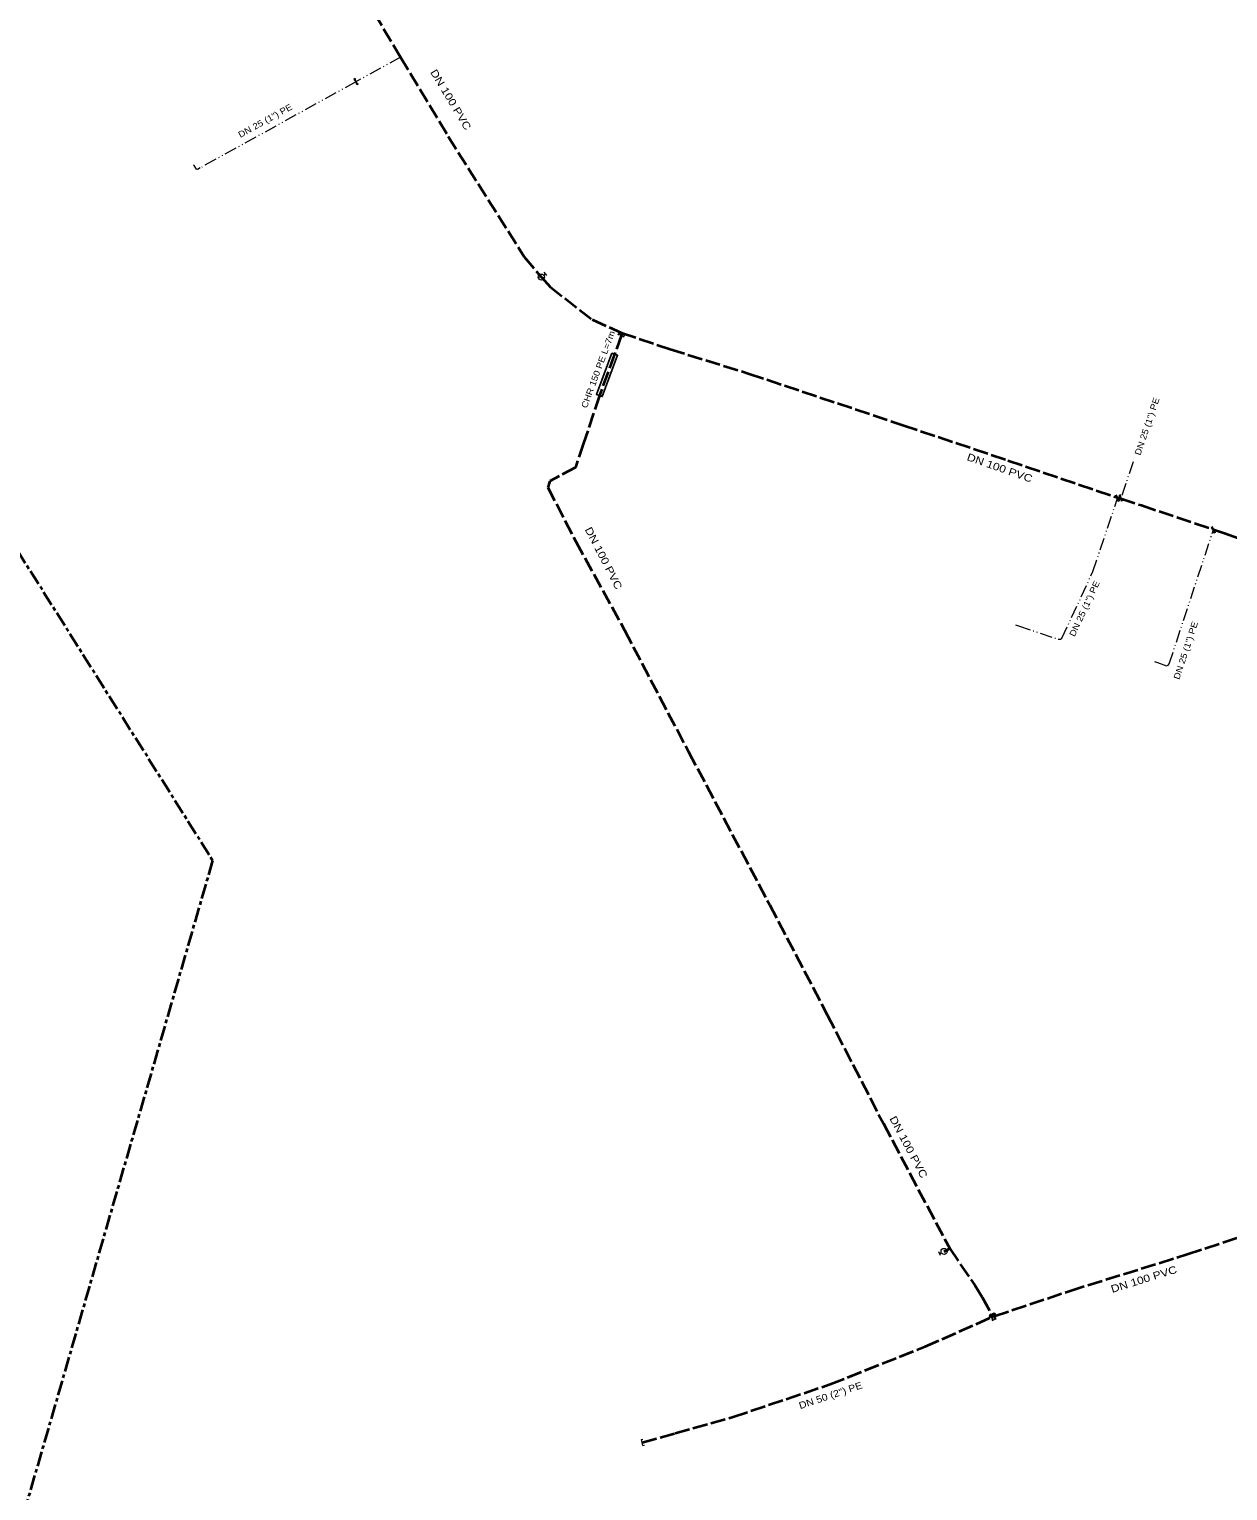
# Model space of a CAD drawing. Extents: x -666789 to -665748, y -1041871 to -1041144.
# Drawn here: x -666272 to -666079.2, y -1041592.9 to -1041357.9 of the extents above; entities that cross this region are included whole.
import ezdxf
from ezdxf.enums import TextEntityAlignment as Align

# ---------------------------------------------------------------- set-up
doc = ezdxf.new("R2010")
doc.units = 0
doc.header["$LTSCALE"] = 0.4
for name, pattern in [('DASH_DOUBLE_DOT', [9.2, 5, -1.2, 0.3, -1.2, 0.3, -1.2]), ('LONG_DASH_SHORT_DASH', [9.9, 6, -1.2, 1.5, -1.2]), ('LONG_DASHED', [7.5, 6, -1.5])]:
    doc.linetypes.add(name, pattern=pattern)
for name, color, linetype, lineweight in [('10', 7, 'Continuous', 13), ('21', 7, 'LONG_DASHED', 35), ('32', 7, 'DASH_DOUBLE_DOT', 13), ('51', 7, 'Continuous', 25), ('63', 7, 'LONG_DASH_SHORT_DASH', 35)]:
    doc.layers.add(name, color=color, linetype=linetype, lineweight=lineweight)
doc.layers.add('29', color=7, linetype='Continuous')
doc.layers.add('39', color=7, linetype='Continuous')

msp = doc.modelspace()

# ---------------------------------------------------------------- linework, layer by layer
at = {"layer": '10'}
for p, q in [((-666189.252, -1041396.944), (-666188.794, -1041397.474)), ((-666189.25, -1041397.405), (-666189.023, -1041397.209)), ((-666190.128, -1041397.695), (-666189.131, -1041397.769)), ((-666125.398, -1041555.084), (-666125.712, -1041554.458)), ((-666125.287, -1041554.637), (-666125.555, -1041554.771)), ((-666173.527, -1041584.655), (-666173.284, -1041584.598)), ((-666173.295, -1041585.629), (-666173.527, -1041584.655)), ((-666173.295, -1041585.629), (-666173.052, -1041585.57))]:
    msp.add_line(p, q, dxfattribs=at)
for points in [[(-666219.818, -1041365.955), (-666219.072, -1041366.685), (-666219.334, -1041366.83), (-666219.555, -1041365.81)], [(-666176.241, -1041407.062), (-666177.284, -1041407.016), (-666177.185, -1041406.733), (-666176.34, -1041407.345)], [(-666097.323, -1041432.929), (-666096.562, -1041433.644), (-666096.822, -1041433.794), (-666097.064, -1041432.779)], [(-666096.753, -1041432.862), (-666096.056, -1041433.639), (-666096.327, -1041433.767), (-666096.481, -1041432.734)], [(-666081.884, -1041438.027), (-666081.165, -1041438.785), (-666081.433, -1041438.92), (-666081.616, -1041437.892)], [(-666117.461, -1041565.069), (-666116.732, -1041564.321), (-666116.586, -1041564.583), (-666117.606, -1041564.806)], [(-666116.854, -1041565.385), (-666117.532, -1041564.59), (-666117.257, -1041564.469), (-666117.129, -1041565.506)], [(-666116.465, -1041565.249), (-666117.068, -1041564.397), (-666116.784, -1041564.301), (-666116.749, -1041565.345)]]:
    msp.add_lwpolyline(points, close=True, dxfattribs=at)
for centre in [(-666189.6283, -1041397.7319), (-666124.84, -1041554.413)]:
    msp.add_circle(centre, 0.5, dxfattribs=at)
at = {"layer": '21'}
for p, q in [((-666221.179, -1041347.519), (-666212.267, -1041362.355)), ((-666176.73, -1041406.682), (-666176.762, -1041407.039)), ((-666096.911, -1041433.192), (-666096.435, -1041433.345)), ((-666124.84, -1041554.413), (-666123.942, -1041553.963)), ((-666117.193, -1041564.988), (-666116.984, -1041564.896)), ((-666117.096, -1041564.695), (-666116.984, -1041564.896)), ((-666116.984, -1041564.896), (-666116.766, -1041564.823)), ((-666173.411, -1041585.142), (-666168.126, -1041583.653))]:
    msp.add_line(p, q, dxfattribs=at)
for points in [[(-666212.267, -1041362.355), (-666204.592, -1041375.133), (-666192.388, -1041394.467), (-666189.629, -1041397.732)], [(-666189.629, -1041397.732), (-666188.221, -1041399.297), (-666181.445, -1041404.57), (-666176.73, -1041406.682)], [(-666176.73, -1041406.682), (-666168.918, -1041409.323), (-666156.197, -1041413.267), (-666131.475, -1041421.524), (-666114.569, -1041427.206), (-666096.911, -1041433.192)], [(-666176.762, -1041407.039), (-666177.837, -1041410.135), (-666180.293, -1041416.763), (-666182.829, -1041424.433), (-666184.152, -1041428.327), (-666188.251, -1041430.57), (-666188.59, -1041431.544), (-666184.103, -1041440.243), (-666176.247, -1041454.509), (-666165.933, -1041474.092), (-666152.928, -1041498.644), (-666143.644, -1041516.379), (-666134.61, -1041533.837), (-666123.942, -1041553.963)], [(-666096.435, -1041433.345), (-666093.095, -1041434.429), (-666081.493, -1041438.311)], [(-666081.493, -1041438.311), (-666079.737, -1041438.912), (-666068.297, -1041442.923), (-666061.852, -1041445.339)], [(-666116.766, -1041564.823), (-666104.583, -1041560.725), (-666085.73, -1041554.871), (-666075.949, -1041551.64)], [(-666123.942, -1041553.963), (-666119.9, -1041559.856), (-666118.713, -1041561.784), (-666117.096, -1041564.695)], [(-666168.126, -1041583.653), (-666158.752, -1041581.012), (-666143.163, -1041575.764), (-666127.903, -1041569.707), (-666117.193, -1041564.988)]]:
    msp.add_lwpolyline(points, dxfattribs=at)
at = {"layer": '32'}
for p, q in [((-666212.267, -1041362.355), (-666219.445, -1041366.32)), ((-666096.943, -1041433.286), (-666096.911, -1041433.192)), ((-666081.524, -1041438.406), (-666081.493, -1041438.311)), ((-666113.363, -1041453.643), (-666112.889, -1041453.802)), ((-666091.011, -1041459.565), (-666090.536, -1041459.721))]:
    msp.add_line(p, q, dxfattribs=at)
for points in [[(-666219.445, -1041366.32), (-666244.527, -1041380.176), (-666244.923, -1041380.402), (-666245.101, -1041380.39), (-666245.501, -1041379.771), (-666245.568, -1041379.667)], [(-666094.439, -1041427.451), (-666096.403, -1041433.25), (-666096.435, -1041433.345)], [(-666112.889, -1041453.802), (-666106.426, -1041455.977), (-666106.128, -1041455.977), (-666105.887, -1041455.793), (-666100.893, -1041445.072), (-666096.943, -1041433.286)], [(-666090.536, -1041459.721), (-666089.085, -1041460.235), (-666088.805, -1041460.153), (-666088.641, -1041459.92), (-666081.524, -1041438.406)]]:
    msp.add_lwpolyline(points, dxfattribs=at)
at = {"layer": '51'}
msp.add_lwpolyline([(-666178.306, -1041409.961), (-666180.762, -1041416.589), (-666179.824, -1041416.937), (-666177.368, -1041410.309)], close=True, dxfattribs=at)
at = {"layer": '63'}
msp.add_lwpolyline([(-666748.889, -1041163.712), (-666788.722, -1041323.504), (-666347.808, -1041324.419), (-666242.501, -1041491.536), (-666296.986, -1041679.715), (-666241.127, -1041826.687), (-665982.439, -1041871.099), (-665998.006, -1041671.474), (-665765.873, -1041672.389), (-665748.475, -1041456.282), (-665860.192, -1041368.831), (-666182.98, -1041263.982), (-666278.671, -1041144.482)], close=True, dxfattribs=at)

# ---------------------------------------------------------------- texts
at = {"layer": '29', "width": 1.2}
for rotation, p in [(300.992, (-666207.548, -1041364.775)), (340.679, (-666121.29, -1041427.139)), (297.285, (-666182.673, -1041438.303)), (297.926, (-666133.672, -1041533.034)), (17.25, (-666097.798, -1041561.079))]:
    msp.add_text('DN 100 PVC', height=1.2, rotation=rotation, dxfattribs=at).set_placement(p)
at = {"layer": '29', "width": 1.15}
msp.add_text('DN 50 (2") PE', height=1.1, rotation=18.606, dxfattribs=at).set_placement((-666142.9305, -1041578.0734), align=Align.CENTER)
at = {"layer": '39', "width": 1.15}
for rotation, p in [(28.917, (-666233.8088, -1041373.0155)), (71.292, (-666091.7236, -1041421.8874)), (65.023, (-666101.806, -1041451.2521)), (71.8, (-666085.5029, -1041457.9242))]:
    msp.add_text('DN 25 (1") PE', height=1, rotation=rotation, dxfattribs=at).set_placement(p, align=Align.CENTER)
at = {"layer": '51', "width": 1.15}
msp.add_text('CHR 150 PE L=7m', height=1, rotation=69.668, dxfattribs=at).set_placement((-666180.0344, -1041412.7467), align=Align.CENTER)

doc.saveas('drawing.dxf')
